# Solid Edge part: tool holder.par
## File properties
Author: Deepak Maini
Template: Normal.par
Last saved by: Robert a Rhodes jr
Revision: 4
Application: Solid Edge
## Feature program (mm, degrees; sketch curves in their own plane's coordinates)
sketch for "unnamed RevolvedProtrusion 1" plane through (0, 0, 0) normal (0, -1, 0) x-axis (1, 0, 0)
  line (0, 50.616) -> (12.5, 50.616)
  line (12.5, 50.616) -> (16.5528, 25.616)
  line (16.5528, 25.616) -> (16.5528, -47.384)
  line (16.5528, -47.384) -> (22.5, -47.384)
  line (22.5, -47.384) -> (22.5, -58.384)
  line (22.5, -58.384) -> (0, -58.384)
  line (0, -58.384) -> (0, 50.616)
revolve "unnamed RevolvedProtrusion 1" add finite 360 deg
sketch for "unnamed Cutout 1" plane through (0, 0, 0) normal (0, -1, 0) x-axis (1, 0, 0)
  line (-9, 8.616) -> (-9, -21.384)
  arc centre (0, -21.384) radius 9 from (9, -21.384) to (-9, -21.384) cw
  line (9, -21.384) -> (9, 8.616)
  arc centre (0, 8.616) radius 9 from (-9, 8.616) to (9, 8.616) cw
extrude "unnamed Cutout 1" cut finite 95.25 symmetric
sketch for "unnamed Hole 1" plane through (0, 0, 50.616) normal (0, 0, 1) x-axis (1, 0, 0)
  hole centre (0, 0) bore radius 8
hole "unnamed Hole 1" through
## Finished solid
Body 1: solid body, 11 faces, 19 edges, 8 vertices.
  Faces by surface: cylinder 5, plane 5, cone 1
  Edges by curve: line 8, circle 6, intersection 5
Bounding box of the edges (mm): 45.000 x 45.000 x 109.000, from (-22.5, -22.5, -58.384) to (22.5, 22.5, 50.616).
Cylindrical faces by radius (mm): R8 x1, R9 x2, R16.5528 x1, R22.5 x1
Conical faces (half-angle, radius in mm at the cone's reference point): 9.2082 deg R12.5 x1
Planar faces by outward normal: +x 1, +z 2, -x 1, -z 1
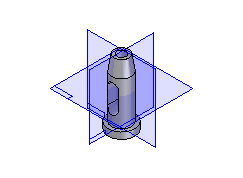
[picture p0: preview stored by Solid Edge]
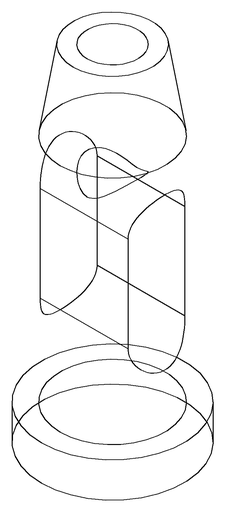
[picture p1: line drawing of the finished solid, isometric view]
